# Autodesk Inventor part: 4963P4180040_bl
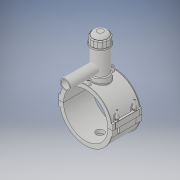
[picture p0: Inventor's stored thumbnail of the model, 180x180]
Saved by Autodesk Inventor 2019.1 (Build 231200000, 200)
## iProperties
Created: 2017-07
Part Number: 4963P4180040_bl
Material: Generic
Document SubType Name: Modeling
Designer: KIM
Density: 1 g/cm^3
Appearance: Default
Author: KIM
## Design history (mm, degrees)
derived "4963P4.ipt"
feature "Solid1::4963P4.ipt" dims "ScaleForDerivedMember" = 10
feature "Solid2::4963P4.ipt" dims "ScaleForDerivedMember" = 10
feature "Solid3::4963P4.ipt" dims "ScaleForDerivedMember" = 10
tag "TaggingFeature1"
body "Solid1"
body "Solid2"
body "Solid3"
other parameters: "d2" = 219 [user parameter], "d3" = 45 [user parameter], "d4" = 118 [user parameter], "d5" = 0 [user parameter], "d6" = 0.1 [user parameter], "d8" = 0 [user parameter], "d19" = 6 [user parameter], "d20" = 6 [user parameter], "d21" = 70.8 [user parameter], "d23" = 0 [user parameter], "d24" = 35.4 [user parameter], "d26" = 0 [user parameter], "d27" = 3 [user parameter], "d28" = 3 [user parameter], "d29" = 3 [user parameter], "d31" = 6 [user parameter], "d32" = 0 [user parameter], "d33" = 0 [user parameter], "d34" = 0.6 [user parameter], "d40" = 108.576 [user parameter], "d41" = 72 [user parameter], "d43" = 0 [user parameter], "d45" = 0 [user parameter], "d47" = 175.2 [user parameter], "d70" = 15 [user parameter], "d72" = 0 [user parameter], "d73" = 6 [user parameter], "d75" = 5 [user parameter], "d76" = 0 [user parameter], "d77" = 9 [user parameter], "d79" = 15 [user parameter], "d80" = 47.2 [user parameter], "d82" = 5 deg [user parameter], "d84" = 4 [user parameter], "d85" = 14 [user parameter], "d86" = 0 [user parameter], "d87" = 3 [user parameter], "d88" = 0 [user parameter], "d89" = 1 [user parameter], "d90" = 1 [user parameter], "d91" = 94.4 [user parameter], "d92" = 0 [user parameter], "d93" = 0.5 [user parameter], "d94" = 94.73684 [user parameter], "d96" = 212.976 [user parameter], "d97" = 2.36 [user parameter], "d98" = 0 [user parameter], "d102" = 1.8 [user parameter], "d120" = 140 deg [user parameter], "d121" = 24.228 [user parameter], "d122" = 20 deg [user parameter], "d123" = 417.6 [user parameter], "d124" = 125.28 [user parameter], "d126" = 0 [user parameter], "d143" = 185.4 [user parameter], "d145" = 22.15385 [user parameter], "d149" = 2.7 [user parameter], "d150" = 24.36923 [user parameter], "d153" = 118 [user parameter], "d154" = 0 [user parameter], "d156" = 104.4 [user parameter], "d157" = 160 deg [user parameter], "d159" = 5.76 [user parameter], "d161" = 2.7 [user parameter], "d162" = 70.8 [user parameter], "d163" = 0 [user parameter], "d167" = 18 [user parameter], "d168" = 101.85366 [user parameter], "d170" = 3.75 [user parameter], "d172" = 0 [user parameter], "d173" = 1 [user parameter], "d176" = 20 deg [user parameter], "d177" = 12.6 [user parameter], "d178" = 28.8 [user parameter], "d180" = 0 [user parameter], "d183" = 11.52 [user parameter], "d184" = 10.08 [user parameter], "d185" = 38.35 [user parameter], "d186" = 38.35 [user parameter], "d187" = 104.4 [user parameter], "d188" = 8.64 [user parameter], "d189" = 12.6 [user parameter], "d190" = 0 [user parameter], "d191" = 156.6 [user parameter], "d193" = 8 [user parameter], "d194" = 4.13 [user parameter], "d195" = 90 deg [user parameter], "d197" = 0 [user parameter], "d199" = 0 [user parameter], "d200" = 14.4 [user parameter], "d202" = 0 [user parameter], "d203" = 177 [user parameter], "d204" = 68.4 [user parameter], "d205" = 50.4 [user parameter], "d206" = 61.2 [user parameter], "d207" = 132.75 [user parameter], "d208" = 138.06 [user parameter], "d209" = 164.61 [user parameter], "d210" = 61.92 [user parameter], "d211" = 72 [user parameter], "d212" = 57.6 [user parameter], "d213" = 36 [user parameter], "d216" = 0 [user parameter], "d217" = 18 [user parameter], "d218" = 18 [user parameter], "d219" = 3.6 [user parameter], "d224" = 0 [user parameter], "d227" = 32 [user parameter], "d228" = 142 [user parameter], "d230" = 3.6 [user parameter], "B_" = 219 [user parameter], "L_" = 118 [user parameter], "d_t" = 6 [user parameter], "H_2" = 177 [user parameter], "H_" = 142 [user parameter], "d1" = 208.8 [user parameter], "d148" = 2.7 [user parameter], "d160" = 2.7 [user parameter], "d169" = 3.75 [user parameter], "d192" = 8 [user parameter]
